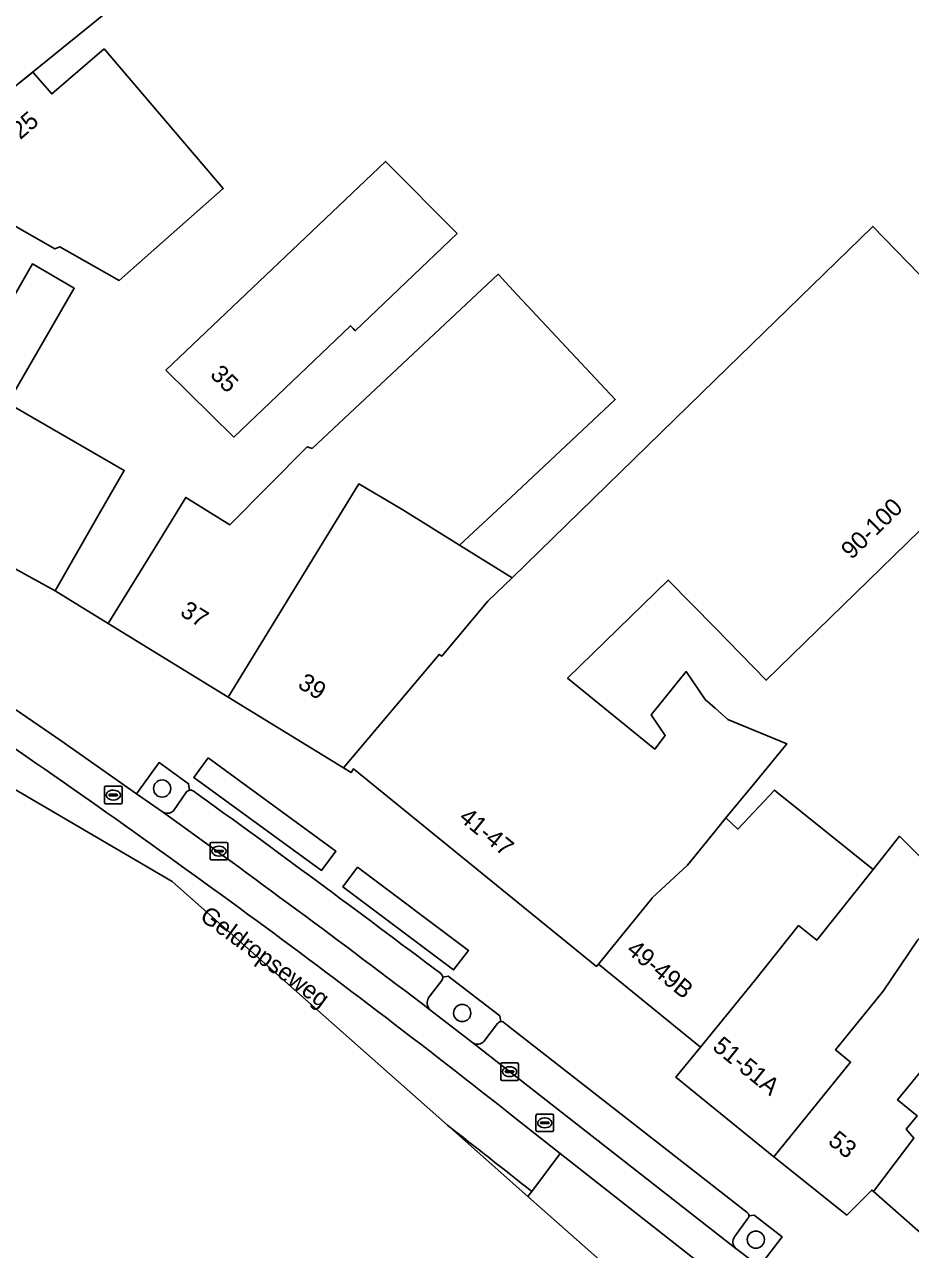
# Model space of a CAD drawing. Extents: x 161771 to 163125, y 382475 to 383179.
# Drawn here: x 161960.8 to 162011.1, y 382779.9 to 382849.5 of the extents above; entities that cross this region are included whole.
import ezdxf

# ---------------------------------------------------------------- set-up
doc = ezdxf.new("R2010")
doc.units = 0
for name, color, linetype in [('IMGEO_Boom', 7, 'Continuous'), ('IMGEO_Erf', 7, 'Continuous'), ('IMGEO_Groenvoorziening', 7, 'Continuous'), ('IMGEO_Kolk', 7, 'Continuous'), ('IMGEO_Openbare_ruimte_label', 7, 'Continuous'), ('IMGEO_Pand', 7, 'Continuous'), ('IMGEO_Pand_nummerreeks', 7, 'Continuous'), ('IMGEO_Parkeervlak_open', 7, 'Continuous'), ('IMGEO_Rijbaan_lokaal_gesloten', 7, 'Continuous'), ('IMGEO_Rijbaan_lokaal_open', 7, 'Continuous'), ('IMGEO_Rioolput', 7, 'Continuous'), ('IMGEO_Voetpad_open', 7, 'Continuous')]:
    doc.layers.add(name, color=color, linetype=linetype)

msp = doc.modelspace()

# ---------------------------------------------------------------- linework, layer by layer
at = {"layer": 'IMGEO_Boom'}
for centre in [(161968.578, 382806.064), (161985.632, 382793.311), (162002.316, 382780.438)]:
    msp.add_circle(centre, 0.489, dxfattribs=at)
at = {"layer": 'IMGEO_Erf'}
for points in [[(161992.377, 382875.411), (161994.282, 382873.624), (161987.798, 382868.366), (161979.104, 382861.42), (161968.728, 382852.865), (161960.405, 382846.092), (161961.238, 382846.769), (161962.308, 382845.524), (161965.278, 382848.079), (161972.054, 382840.15), (161966.134, 382834.922), (161962.771, 382836.845), (161962.488, 382836.719), (161958.294, 382839.117)], [(161959.161, 382832.328), (161961.207, 382835.864), (161963.586, 382834.487), (161959.813, 382827.965), (161966.426, 382824.139), (161965.007, 382821.675), (161962.509, 382817.293), (161965.52, 382815.44), (161968.136, 382819.701), (161969.918, 382822.603), (161972.432, 382821.051), (161976.821, 382825.479), (161977.107, 382825.392), (161987.672, 382835.277), (161988.758, 382834.116), (161994.328, 382828.161), (161988.411, 382822.624), (161985.483, 382819.885), (161988.465, 382818.044), (162000, 382829.276), (162008.957, 382837.998), (162018.897, 382827.792), (162002.91, 382812.221), (162000, 382815.195), (161997.344, 382817.91), (161991.621, 382812.339), (161996.583, 382808.309), (161997.165, 382809.078), (161996.374, 382810.26), (161998.355, 382812.71), (161999.44, 382811.125), (162000, 382810.628), (162000.728, 382809.981), (162004.072, 382808.611), (162002.183, 382806.29), (162000.614, 382804.402), (162001.286, 382803.766), (162003.378, 382805.977), (162003.518, 382805.864), (162007.823, 382802.394), (162008.976, 382801.465), (162010.483, 382803.357), (162013.343, 382800.477)]]:
    msp.add_lwpolyline(points, dxfattribs=at)
msp.add_lwpolyline([(161985.349, 382837.596), (161979.55, 382832.07), (161979.432, 382832.194), (161979.282, 382832.352), (161972.65, 382826.032), (161968.798, 382829.841), (161981.279, 382841.687)], close=True, dxfattribs=at)
at = {"layer": 'IMGEO_Groenvoorziening'}
for points in [[(161971.2, 382807.801), (161970.389, 382806.691), (161977.639, 382801.416), (161978.452, 382802.505)], [(161979.684, 382801.595), (161978.846, 382800.484), (161985.141, 382795.761), (161985.98, 382796.873)]]:
    msp.add_lwpolyline(points, close=True, dxfattribs=at)
for points in [[(161970.143, 382805.964), (161970.084, 382806.342), (161968.403, 382807.536), (161967.125, 382805.772)], [(161967.125, 382805.772), (161968.592, 382804.746)], [(161969.217, 382804.795), (161969.97, 382805.882)], [(161984.476, 382795.161), (161983.706, 382794.162)], [(161987.834, 382792.825), (161987.774, 382793.145), (161984.84, 382795.398), (161984.523, 382795.348)], [(161983.779, 382793.515), (161986.232, 382791.616)], [(161986.859, 382791.7), (161987.636, 382792.72)], [(162001.846, 382781.618), (162001.108, 382780.604)], [(162001.183, 382779.934), (162002.181, 382779.172), (162002.498, 382778.903), (162003.822, 382780.597), (162002.23, 382781.821), (162001.928, 382781.788)]]:
    msp.add_lwpolyline(points, dxfattribs=at)
for centre, radius, start, end in [((161970.202, 382805.615), 0.354, 99.6586, 131.06222), ((161968.873, 382805.167), 0.507, 236.25841, 312.70723), ((161984.244, 382795.319), 0.28, 325.77633, 6.00704), ((161984.239, 382793.895), 0.597, 153.36116, 219.51358), ((161987.849, 382792.558), 0.267, 93.15744, 142.71684), ((161986.497, 382792.021), 0.484, 236.81426, 318.44685), ((162001.697, 382781.795), 0.231, 310.17582, 358.32323), ((162001.517, 382780.311), 0.503, 144.35005, 228.42418)]:
    msp.add_arc(centre, radius, start, end, dxfattribs=at)
at = {"layer": 'IMGEO_Kolk'}
for p, q in [((161971.31, 382802.083), (161971.31, 382802.935)), ((161971.385, 382803.009), (161972.237, 382803.009)), ((161971.798, 382802.789), (161971.823, 382802.789)), ((161972.311, 382802.935), (161972.311, 382802.083)), ((161971.569, 382802.503), (161971.569, 382802.515)), ((161972.007, 382802.466), (161971.609, 382802.466)), ((161971.612, 382802.552), (161972.01, 382802.552)), ((161971.821, 382802.229), (161971.796, 382802.229)), ((161972.053, 382802.515), (161972.053, 382802.503)), ((161972.237, 382802.009), (161971.385, 382802.009)), ((161987.82, 382789.558), (161987.82, 382790.41)), ((161987.895, 382790.484), (161988.747, 382790.484)), ((161988.308, 382790.264), (161988.333, 382790.264)), ((161988.821, 382790.41), (161988.821, 382789.558)), ((161988.079, 382789.978), (161988.079, 382789.99)), ((161988.517, 382789.941), (161988.119, 382789.941)), ((161988.122, 382790.027), (161988.52, 382790.027)), ((161988.331, 382789.704), (161988.306, 382789.704)), ((161988.563, 382789.99), (161988.563, 382789.978)), ((161988.747, 382789.484), (161987.895, 382789.484))]:
    msp.add_line(p, q, dxfattribs=at)
for points in [[(161971.31, 382802.083), (161971.31, 382802.935)], [(161971.385, 382803.009), (161972.237, 382803.009)], [(161972.311, 382802.935), (161972.311, 382802.083)], [(161972.237, 382802.009), (161971.385, 382802.009)], [(161987.82, 382789.558), (161987.82, 382790.41)], [(161987.895, 382790.484), (161988.747, 382790.484)], [(161988.821, 382790.41), (161988.821, 382789.558)], [(161988.747, 382789.484), (161987.895, 382789.484)]]:
    msp.add_lwpolyline(points, dxfattribs=at)
for centre, radius, start, end in [((161971.387, 382802.933), 0.0765, 91.55205, 178.44795), ((161971.387, 382802.933), 0.0765, 91.55205, 178.44795), ((161972.235, 382802.933), 0.0765, 1.55205, 88.44795), ((161972.235, 382802.933), 0.0765, 1.55205, 88.44795), ((161971.387, 382802.085), 0.0765, 181.55205, 268.44795), ((161971.387, 382802.085), 0.0765, 181.55205, 268.44795), ((161971.609, 382802.512), 0.0403, 85.87752, 175.75265), ((161971.606, 382802.502), 0.0366, 178.93798, 274.71019), ((161972.01, 382802.509), 0.043, 264.86636, 352.45326), ((161972.014, 382802.514), 0.0386, 1.73085, 96.63898), ((161972.235, 382802.085), 0.0765, 271.55205, 358.44795), ((161972.235, 382802.085), 0.0765, 271.55205, 358.44795), ((161987.897, 382790.408), 0.0765, 91.55205, 178.44795), ((161987.897, 382790.408), 0.0765, 91.55205, 178.44795), ((161988.745, 382790.408), 0.0765, 1.55205, 88.44795), ((161988.745, 382790.408), 0.0765, 1.55205, 88.44795), ((161987.897, 382789.56), 0.0765, 181.55205, 268.44795), ((161987.897, 382789.56), 0.0765, 181.55205, 268.44795), ((161988.119, 382789.987), 0.0403, 85.87752, 175.75265), ((161988.116, 382789.977), 0.0366, 178.93798, 274.71019), ((161988.52, 382789.984), 0.043, 264.86636, 352.45326), ((161988.524, 382789.989), 0.0386, 1.73085, 96.63898), ((161988.745, 382789.56), 0.0765, 271.55205, 358.44795), ((161988.745, 382789.56), 0.0765, 271.55205, 358.44795)]:
    msp.add_arc(centre, radius, start, end, dxfattribs=at)
for centre, major_axis, ratio, start_param, end_param in [((161971.797, 382802.509), (-0.387, 0.002), 0.722429, 4.712389, 7.853982), ((161971.822, 382802.509), (-0.39, 0.002), 0.717154, 1.570796, 4.712389), ((161988.307, 382789.984), (-0.387, 0.002), 0.722429, 4.712389, 7.853982), ((161988.332, 382789.984), (-0.39, 0.002), 0.717154, 1.570796, 4.712389)]:
    msp.add_ellipse(centre, major_axis=major_axis, ratio=ratio, start_param=start_param, end_param=end_param, dxfattribs=at)
at = {"layer": 'IMGEO_Pand'}
for points in [[(161958.915, 382832.47), (161953.924, 382835.358), (161958.294, 382839.117), (161962.488, 382836.719), (161962.771, 382836.845), (161966.134, 382834.922), (161972.054, 382840.15), (161965.278, 382848.079), (161962.308, 382845.524), (161961.238, 382846.769), (161960.405, 382846.092), (161958.508, 382844.465), (161954.479, 382841.299), (161949.455, 382837.351), (161944.451, 382828.498), (161943.963, 382827.66), (161953.171, 382822.43)], [(161985.349, 382837.596), (161981.279, 382841.687), (161968.798, 382829.841), (161972.65, 382826.032), (161979.282, 382832.352), (161979.432, 382832.194), (161979.55, 382832.07)], [(162018.897, 382827.792), (162008.957, 382837.998), (162000, 382829.276), (161988.465, 382818.044), (161987.088, 382816.703), (161984.481, 382813.588), (161984.321, 382813.687), (161978.893, 382807.245), (161979.326, 382806.979), (161979.452, 382807.183), (161993.267, 382795.96), (161993.375, 382796.093), (161996.4, 382799.825), (161996.43, 382799.862), (161998.425, 382801.707), (162000, 382803.646), (162000.614, 382804.402), (162002.183, 382806.29), (162004.072, 382808.611), (162000.728, 382809.981), (162000, 382810.628), (161999.44, 382811.125), (161998.355, 382812.71), (161996.374, 382810.26), (161997.165, 382809.078), (161996.583, 382808.309), (161991.621, 382812.339), (161997.344, 382817.91), (162000, 382815.195), (162002.91, 382812.221)], [(161959.813, 382827.965), (161963.586, 382834.487), (161961.207, 382835.864), (161959.161, 382832.328), (161958.915, 382832.47), (161953.171, 382822.43), (161962.509, 382817.293), (161965.007, 382821.675), (161966.426, 382824.139)], [(161988.758, 382834.116), (161987.672, 382835.277), (161977.107, 382825.392), (161976.821, 382825.479), (161972.432, 382821.051), (161969.918, 382822.603), (161968.136, 382819.701), (161965.52, 382815.44), (161972.332, 382811.265), (161979.752, 382823.375), (161982.255, 382821.899), (161985.483, 382819.885), (161988.411, 382822.624), (161994.328, 382828.161)], [(161984.321, 382813.687), (161984.481, 382813.588), (161987.088, 382816.703), (161988.465, 382818.044), (161985.483, 382819.885), (161982.255, 382821.899), (161979.752, 382823.375), (161972.332, 382811.265), (161978.893, 382807.245)], [(162008.976, 382801.465), (162007.823, 382802.394), (162003.518, 382805.864), (162003.378, 382805.977), (162001.286, 382803.766), (162000.614, 382804.402), (162000, 382803.646), (161998.425, 382801.707), (161996.43, 382799.862), (161996.4, 382799.825), (161993.375, 382796.093), (161999.165, 382791.37), (162000, 382792.399), (162002.233, 382795.15), (162004.747, 382798.281), (162005.777, 382797.449)], [(162011.528, 382797.48), (162014.005, 382799.81), (162013.343, 382800.477), (162010.483, 382803.357), (162008.976, 382801.465), (162005.777, 382797.449), (162004.747, 382798.281), (162002.233, 382795.15), (162000, 382792.399), (161999.165, 382791.37), (161997.776, 382789.66), (162000, 382787.854), (162003.337, 382785.143), (162007.703, 382790.52), (162006.847, 382791.215), (162009.56, 382794.557)], [(162014.006, 382793.154), (162014.966, 382794.089), (162014.073, 382795.007), (162016.114, 382796.992), (162016.459, 382797.328), (162019.062, 382799.858), (162015.975, 382803.035), (162013.343, 382800.477), (162014.005, 382799.81), (162011.528, 382797.48), (162009.56, 382794.557), (162006.847, 382791.215), (162007.703, 382790.52), (162003.337, 382785.143), (162007.486, 382781.832), (162008.9, 382783.259), (162008.994, 382783.177), (162011.304, 382786.195), (162010.863, 382786.72), (162011.481, 382787.481), (162010.376, 382788.379), (162012.441, 382790.923), (162013.088, 382791.763), (162012.855, 382791.952)], [(162019.129, 382787.826), (162016.154, 382790.92), (162014.006, 382793.154), (162012.855, 382791.952), (162013.088, 382791.763), (162012.441, 382790.923), (162010.376, 382788.379), (162011.481, 382787.481), (162010.863, 382786.72), (162011.304, 382786.195), (162008.994, 382783.177), (162012.95, 382779.713), (162014.703, 382779.815), (162020.641, 382786.362), (162020.385, 382786.52)]]:
    msp.add_lwpolyline(points, close=True, dxfattribs=at)
at = {"layer": 'IMGEO_Parkeervlak_open'}
for points in [[(161969.97, 382805.882), (161969.217, 382804.795)], [(161983.706, 382794.162), (161984.476, 382795.161)], [(161987.636, 382792.72), (161986.859, 382791.7)], [(162001.819, 382781.989), (161988.024, 382792.76)], [(161986.232, 382791.616), (162001.183, 382779.934)], [(162001.108, 382780.604), (162001.846, 382781.618)]]:
    msp.add_lwpolyline(points, dxfattribs=at)
for centre, radius, start, end in [((161970.202, 382805.615), 0.354, 99.6586, 131.06222), ((161970.197, 382805.625), 0.343, 65.36843, 99.02337), ((161536.2, 382203.194), 742.817, 52.886717, 54.235752), ((161968.873, 382805.167), 0.507, 236.25841, 312.70723), ((161569.697, 382249.46), 683.71, 52.725083, 54.308024), ((161984.239, 382795.321), 0.285, 5.46677, 53.22166), ((161984.244, 382795.319), 0.28, 325.77633, 6.00704), ((161984.239, 382793.895), 0.597, 153.36116, 219.51358), ((161987.849, 382792.558), 0.267, 93.15744, 142.71684), ((161987.848, 382792.556), 0.269, 49.19145, 93.03637), ((161986.497, 382792.021), 0.484, 236.81426, 318.44685), ((162001.697, 382781.793), 0.231, 358.86942, 58.07152), ((162001.697, 382781.795), 0.231, 310.17582, 358.32323), ((162001.517, 382780.311), 0.503, 144.35005, 228.42418)]:
    msp.add_arc(centre, radius, start, end, dxfattribs=at)
at = {"layer": 'IMGEO_Rijbaan_lokaal_gesloten'}
for points in [[(161968.592, 382804.746), (161967.125, 382805.772), (161962.834, 382808.772), (161956.727, 382812.959), (161956.311, 382813.259)], [(161988.613, 382787.368), (161991.205, 382785.331), (162001.812, 382776.997), (162004.745, 382774.628), (162005.953, 382776.124), (162002.498, 382778.903), (162002.181, 382779.172), (162001.183, 382779.934), (161986.232, 382791.616), (161983.779, 382793.515)], [(161984.797, 382786.939), (161989.366, 382782.899), (161989.58, 382783.178)]]:
    msp.add_lwpolyline(points, dxfattribs=at)
for centre, radius, start, end in [((161663.73, 382376.996), 523.406, 51.63204, 55.9449), ((161569.697, 382249.46), 683.71, 52.725083, 54.308024), ((161623.915, 382323.028), 587.749, 51.52705, 52.120228)]:
    msp.add_arc(centre, radius, start, end, dxfattribs=at)
at = {"layer": 'IMGEO_Rijbaan_lokaal_open'}
for points in [[(161960.405, 382846.092), (161968.728, 382852.865), (161979.104, 382861.42), (161987.798, 382868.366), (161994.282, 382873.624), (161992.377, 382875.411)], [(161951.892, 382810.876), (161969.14, 382800.781), (161984.797, 382786.939)], [(161989.58, 382783.178), (161991.205, 382785.331), (161988.613, 382787.368)], [(161999.533, 382774.178), (162000.068, 382774.83), (162001.812, 382776.997), (161991.205, 382785.331), (161989.58, 382783.178), (161989.366, 382782.899), (161995.879, 382777.141), (161999.533, 382774.178)]]:
    msp.add_lwpolyline(points, dxfattribs=at)
for centre, radius, start, end in [((161663.73, 382376.996), 523.406, 51.63204, 55.9449), ((161623.915, 382323.028), 587.749, 51.52705, 52.120228)]:
    msp.add_arc(centre, radius, start, end, dxfattribs=at)
at = {"layer": 'IMGEO_Rioolput'}
for p, q in [((161965.303, 382805.268), (161965.303, 382806.12)), ((161965.378, 382806.194), (161966.23, 382806.194)), ((161965.562, 382805.688), (161965.562, 382805.7)), ((161966, 382805.651), (161965.602, 382805.651)), ((161965.605, 382805.737), (161966.003, 382805.737)), ((161965.791, 382805.974), (161965.816, 382805.974)), ((161966.046, 382805.7), (161966.046, 382805.688)), ((161966.304, 382806.12), (161966.304, 382805.268)), ((161966.23, 382805.194), (161965.378, 382805.194)), ((161965.814, 382805.414), (161965.789, 382805.414)), ((161989.824, 382786.648), (161989.824, 382787.5)), ((161989.899, 382787.574), (161990.751, 382787.574)), ((161990.825, 382787.5), (161990.825, 382786.648)), ((161990.083, 382787.068), (161990.083, 382787.08)), ((161990.521, 382787.031), (161990.123, 382787.031)), ((161990.126, 382787.117), (161990.524, 382787.117)), ((161990.335, 382786.794), (161990.31, 382786.794)), ((161990.312, 382787.354), (161990.337, 382787.354)), ((161990.567, 382787.08), (161990.567, 382787.068)), ((161990.751, 382786.574), (161989.899, 382786.574))]:
    msp.add_line(p, q, dxfattribs=at)
for points in [[(161965.303, 382805.268), (161965.303, 382806.12)], [(161965.378, 382806.194), (161966.23, 382806.194)], [(161966.304, 382806.12), (161966.304, 382805.268)], [(161966.23, 382805.194), (161965.378, 382805.194)], [(161989.824, 382786.648), (161989.824, 382787.5)], [(161989.899, 382787.574), (161990.751, 382787.574)], [(161990.825, 382787.5), (161990.825, 382786.648)], [(161990.751, 382786.574), (161989.899, 382786.574)]]:
    msp.add_lwpolyline(points, dxfattribs=at)
for centre, radius, start, end in [((161965.38, 382806.118), 0.0765, 91.55205, 178.44795), ((161965.38, 382806.118), 0.0765, 91.55205, 178.44795), ((161965.602, 382805.697), 0.0403, 85.87752, 175.75265), ((161965.599, 382805.687), 0.0366, 178.93798, 274.71019), ((161966.003, 382805.694), 0.043, 264.86636, 352.45326), ((161966.007, 382805.699), 0.0386, 1.73085, 96.63898), ((161966.228, 382806.118), 0.0765, 1.55205, 88.44795), ((161966.228, 382806.118), 0.0765, 1.55205, 88.44795), ((161965.38, 382805.27), 0.0765, 181.55205, 268.44795), ((161965.38, 382805.27), 0.0765, 181.55205, 268.44795), ((161966.228, 382805.27), 0.0765, 271.55205, 358.44795), ((161966.228, 382805.27), 0.0765, 271.55205, 358.44795), ((161989.901, 382787.498), 0.0765, 91.55205, 178.44795), ((161989.901, 382787.498), 0.0765, 91.55205, 178.44795), ((161990.749, 382787.498), 0.0765, 1.55205, 88.44795), ((161990.749, 382787.498), 0.0765, 1.55205, 88.44795), ((161990.123, 382787.077), 0.0403, 85.87752, 175.75265), ((161990.12, 382787.067), 0.0366, 178.93798, 274.71019), ((161990.524, 382787.074), 0.043, 264.86636, 352.45326), ((161990.528, 382787.079), 0.0386, 1.73085, 96.63898), ((161989.901, 382786.65), 0.0765, 181.55205, 268.44795), ((161989.901, 382786.65), 0.0765, 181.55205, 268.44795), ((161990.749, 382786.65), 0.0765, 271.55205, 358.44795), ((161990.749, 382786.65), 0.0765, 271.55205, 358.44795)]:
    msp.add_arc(centre, radius, start, end, dxfattribs=at)
for centre, major_axis, ratio, start_param, end_param in [((161965.79, 382805.694), (-0.387, 0.002), 0.722429, 4.712389, 7.853982), ((161965.815, 382805.694), (-0.39, 0.002), 0.717154, 1.570796, 4.712389), ((161990.311, 382787.074), (-0.387, 0.002), 0.722429, 4.712389, 7.853982), ((161990.336, 382787.074), (-0.39, 0.002), 0.717154, 1.570796, 4.712389)]:
    msp.add_ellipse(centre, major_axis=major_axis, ratio=ratio, start_param=start_param, end_param=end_param, dxfattribs=at)
at = {"layer": 'IMGEO_Voetpad_open'}
for points in [[(162013.278, 382773.96), (162016.666, 382777.602), (162014.703, 382779.815), (162012.95, 382779.713), (162008.994, 382783.177), (162008.9, 382783.259), (162007.486, 382781.832), (162003.337, 382785.143), (162000, 382787.854), (161997.776, 382789.66), (161999.165, 382791.37), (161993.375, 382796.093), (161993.267, 382795.96), (161979.452, 382807.183), (161979.326, 382806.979), (161978.893, 382807.245), (161972.332, 382811.265), (161965.52, 382815.44), (161962.509, 382817.293), (161953.171, 382822.43), (161943.963, 382827.66), (161944.451, 382828.498), (161919.878, 382842.285)], [(161955.504, 382816.122), (161955.832, 382816.19), (161957.542, 382814.993), (161956.311, 382813.259), (161956.727, 382812.959), (161962.834, 382808.772), (161967.125, 382805.772), (161968.403, 382807.536), (161970.084, 382806.342), (161970.143, 382805.964)], [(161984.523, 382795.348), (161984.84, 382795.398), (161987.774, 382793.145), (161987.834, 382792.825)], [(161988.024, 382792.76), (162001.819, 382781.989)], [(162001.928, 382781.788), (162002.23, 382781.821), (162003.822, 382780.597), (162002.498, 382778.903), (162005.953, 382776.124), (162008.878, 382773.768)]]:
    msp.add_lwpolyline(points, dxfattribs=at)
for points in [[(161971.2, 382807.801), (161978.452, 382802.505), (161977.639, 382801.416), (161970.389, 382806.691)], [(161979.684, 382801.595), (161985.98, 382796.873), (161985.141, 382795.761), (161978.846, 382800.484)]]:
    msp.add_lwpolyline(points, close=True, dxfattribs=at)
for centre, radius, start, end in [((161970.197, 382805.625), 0.343, 65.36843, 99.02337), ((161536.2, 382203.194), 742.817, 52.886717, 54.235752), ((161984.239, 382795.321), 0.285, 5.46677, 53.22166), ((161987.848, 382792.556), 0.269, 49.19145, 93.03637), ((162001.697, 382781.793), 0.231, 358.86942, 58.07152)]:
    msp.add_arc(centre, radius, start, end, dxfattribs=at)

# ---------------------------------------------------------------- texts
at = {"layer": 'IMGEO_Openbare_ruimte_label'}
msp.add_text('Geldropseweg', height=1, rotation=323.78312, dxfattribs=at).set_placement((161970.656, 382798.658))
at = {"layer": 'IMGEO_Pand_nummerreeks'}
for s, rotation, p in [('25', 40.61698, (161960.516, 382842.894)), ('35', 315.32075, (161971.254, 382829.522)), ('90-100', 44.2438, (162007.752, 382819.031)), ('37', 328.49878, (161969.538, 382815.933)), ('39', 328.49878, (161976.224, 382811.836)), ('41-47', 320.91282, (161985.38, 382804.3)), ('49-49B', 320.7925, (161994.901, 382796.785)), ('51-51A', 320.91855, (161999.795, 382791.287)), ('53', 320.91282, (162006.362, 382785.932))]:
    msp.add_text(s, height=1, rotation=rotation, dxfattribs=at).set_placement(p)

doc.saveas('drawing.dxf')
